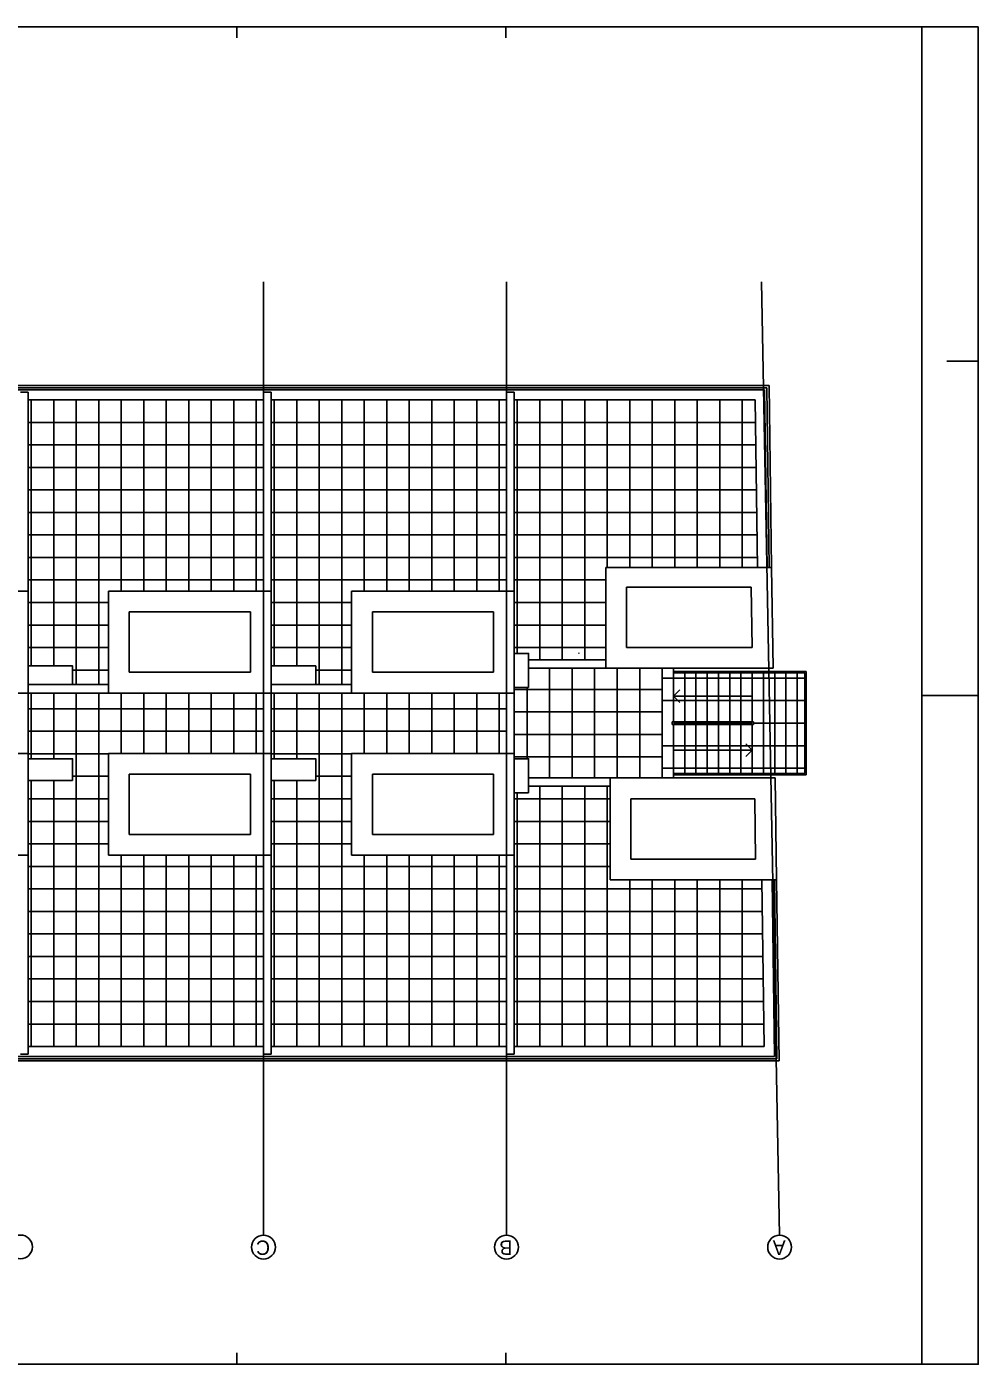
# Model space of a CAD drawing. Extents: x 1278 to 1356, y -443 to -224.
# Drawn here: x 1334.82 to 1355.97, y -253.66 to -223.96 of the extents above; entities that cross this region are included whole.
import ezdxf

# ---------------------------------------------------------------- set-up
doc = ezdxf.new("R2010")
doc.units = 0
for name, color, linetype in [('estrutura-eixos', 7, 'Continuous'), ('Level 10', 7, 'Continuous'), ('Level 2', 7, 'Continuous'), ('Level 21', 7, 'Continuous'), ('Level 60', 7, 'Continuous'), ('Level 62', 7, 'Continuous'), ('Level 66', 7, 'Continuous'), ('Level 68', 7, 'Continuous'), ('Level 70', 7, 'Continuous')]:
    doc.layers.add(name, color=color, linetype=linetype)

msp = doc.modelspace()

# ---------------------------------------------------------------- linework, layer by layer
at = {"layer": 'estrutura-eixos'}
for p, q in [((1340.084, -229.62), (1340.084, -250.792)), ((1345.484, -250.792), (1345.484, -229.62)), ((1351.148, -229.62), (1351.553, -250.792))]:
    msp.add_line(p, q, dxfattribs=at)
at = {"layer": 'Level 10'}
for p, q in [((1348.943, -240.624), (1348.943, -238.224)), ((1352.113, -238.424), (1348.943, -238.424)), ((1349.193, -239.394), (1349.193, -238.224)), ((1349.443, -239.394), (1349.443, -238.304)), ((1349.693, -239.394), (1349.693, -238.304)), ((1349.943, -239.394), (1349.943, -238.304)), ((1350.193, -239.394), (1350.193, -238.304)), ((1350.443, -239.394), (1350.443, -238.304)), ((1350.693, -239.394), (1350.693, -238.304)), ((1350.943, -239.394), (1350.943, -238.304)), ((1351.193, -240.544), (1351.193, -238.304)), ((1351.443, -240.544), (1351.443, -238.304)), ((1351.693, -240.544), (1351.693, -238.304)), ((1351.943, -240.544), (1351.943, -238.304)), ((1352.113, -238.924), (1348.943, -238.924)), ((1349.193, -240.624), (1349.193, -239.454)), ((1349.443, -240.544), (1349.443, -239.454)), ((1349.693, -240.544), (1349.693, -239.454)), ((1349.943, -240.544), (1349.943, -239.454)), ((1350.693, -240.544), (1350.693, -239.454)), ((1350.943, -240.544), (1350.943, -239.454)), ((1352.113, -239.424), (1350.973, -239.424)), ((1352.113, -239.924), (1348.943, -239.924)), ((1352.113, -240.424), (1348.943, -240.424))]:
    msp.add_line(p, q, dxfattribs=at)
at = {"layer": 'Level 2'}
for p, q in [((1318.543, -231.924), (1345.543, -231.924)), ((1351.318, -231.924), (1345.543, -231.924)), ((1351.318, -231.924), (1351.374, -235.964)), ((1334.854, -232.244), (1340.083, -232.244)), ((1340.254, -232.244), (1345.483, -232.244)), ((1351.268, -231.974), (1345.543, -231.974)), ((1351.219, -232.024), (1345.543, -232.024)), ((1351.007, -232.244), (1345.654, -232.244)), ((1351.007, -232.244), (1351.058, -235.964)), ((1351.219, -232.024), (1351.274, -235.964)), ((1351.268, -231.974), (1351.324, -235.964)), ((1348.152, -236.406), (1350.92, -236.406)), ((1348.152, -236.406), (1348.152, -237.746)), ((1337.103, -236.954), (1339.794, -236.954)), ((1337.103, -236.954), (1337.103, -238.294)), ((1342.503, -236.954), (1345.194, -236.954)), ((1342.503, -236.954), (1342.503, -238.294)), ((1348.152, -237.746), (1350.939, -237.746)), ((1337.103, -238.294), (1339.794, -238.294)), ((1342.503, -238.294), (1345.194, -238.294)), ((1349.193, -238.224), (1349.193, -239.394)), ((1349.193, -238.274), (1352.143, -238.274)), ((1349.193, -238.304), (1352.113, -238.304)), ((1349.443, -238.304), (1349.443, -239.394)), ((1349.693, -238.304), (1349.693, -239.394)), ((1349.943, -238.304), (1349.943, -239.394)), ((1350.193, -238.304), (1350.193, -239.394)), ((1350.443, -238.304), (1350.443, -239.394)), ((1350.693, -238.304), (1350.693, -239.394)), ((1350.943, -238.304), (1350.943, -239.394)), ((1352.113, -238.304), (1352.113, -240.544)), ((1352.143, -238.274), (1352.143, -240.574)), ((1349.335, -238.683), (1349.193, -238.824)), ((1350.943, -238.824), (1349.193, -238.824)), ((1349.335, -238.965), (1349.193, -238.824)), ((1349.163, -239.394), (1350.973, -239.394)), ((1349.163, -239.394), (1349.163, -239.454)), ((1349.163, -239.454), (1350.973, -239.454)), ((1349.193, -239.424), (1350.943, -239.424)), ((1349.193, -239.454), (1349.193, -240.574)), ((1349.443, -239.454), (1349.443, -240.544)), ((1349.693, -239.454), (1349.693, -240.544)), ((1349.943, -239.454), (1349.943, -240.544)), ((1350.193, -239.454), (1350.193, -240.544)), ((1350.443, -239.454), (1350.443, -240.544)), ((1350.693, -239.454), (1350.693, -240.544)), ((1350.943, -239.454), (1350.943, -240.544)), ((1350.973, -239.394), (1350.973, -239.454)), ((1350.802, -239.883), (1350.943, -240.024)), ((1349.193, -240.024), (1350.943, -240.024)), ((1350.802, -240.165), (1350.943, -240.024)), ((1337.103, -240.554), (1339.794, -240.554)), ((1337.103, -240.554), (1337.103, -241.894)), ((1342.503, -240.554), (1345.194, -240.554)), ((1342.503, -240.554), (1342.503, -241.894)), ((1349.193, -240.544), (1352.113, -240.544)), ((1349.193, -240.574), (1349.193, -240.624)), ((1349.193, -240.574), (1352.143, -240.574)), ((1348.245, -241.104), (1351.001, -241.104)), ((1348.245, -241.104), (1348.245, -242.444)), ((1337.103, -241.894), (1339.794, -241.894)), ((1342.503, -241.894), (1345.194, -241.894)), ((1348.245, -242.444), (1351.02, -242.444)), ((1351.156, -242.908), (1351.207, -246.604)), ((1351.386, -242.904), (1351.441, -246.824)), ((1351.436, -242.904), (1351.492, -246.874)), ((1351.486, -242.904), (1351.543, -246.924)), ((1334.854, -246.604), (1340.083, -246.604)), ((1340.254, -246.604), (1345.483, -246.604)), ((1351.207, -246.604), (1345.654, -246.604)), ((1351.441, -246.824), (1345.493, -246.824)), ((1351.492, -246.874), (1345.493, -246.874)), ((1351.543, -246.924), (1345.493, -246.924))]:
    msp.add_line(p, q, dxfattribs=at)
at = {"layer": 'Level 21'}
for p, q in [((1334.923, -238.154), (1334.923, -232.244)), ((1335.423, -238.154), (1335.423, -232.244)), ((1335.923, -238.564), (1335.923, -232.244)), ((1336.423, -238.564), (1336.423, -232.244)), ((1336.923, -236.494), (1336.923, -232.244)), ((1337.423, -236.494), (1337.423, -232.244)), ((1337.923, -236.494), (1337.923, -232.244)), ((1338.423, -236.494), (1338.423, -232.244)), ((1338.923, -236.494), (1338.923, -232.244)), ((1339.423, -236.494), (1339.423, -232.244)), ((1339.923, -236.494), (1339.923, -232.244)), ((1340.323, -238.154), (1340.323, -232.244)), ((1340.823, -238.154), (1340.823, -232.244)), ((1341.323, -238.564), (1341.323, -232.244)), ((1341.823, -238.564), (1341.823, -232.244)), ((1342.323, -236.494), (1342.323, -232.244)), ((1342.823, -236.494), (1342.823, -232.244)), ((1343.323, -236.494), (1343.323, -232.244)), ((1343.823, -236.494), (1343.823, -232.244)), ((1344.323, -236.494), (1344.323, -232.244)), ((1344.823, -236.494), (1344.823, -232.244)), ((1345.323, -236.494), (1345.323, -232.244)), ((1345.723, -237.874), (1345.723, -232.244)), ((1346.223, -238.016), (1346.223, -232.244)), ((1346.723, -238.016), (1346.723, -232.244)), ((1347.223, -238.016), (1347.223, -232.244)), ((1347.723, -235.964), (1347.723, -232.244)), ((1348.223, -235.964), (1348.223, -232.244)), ((1348.723, -235.964), (1348.723, -232.244)), ((1349.223, -235.964), (1349.223, -232.244)), ((1349.723, -235.964), (1349.723, -232.244)), ((1350.223, -235.964), (1350.223, -232.244)), ((1350.723, -235.964), (1350.723, -232.244)), ((1334.854, -232.744), (1340.083, -232.744)), ((1340.254, -232.744), (1345.483, -232.744)), ((1345.654, -232.744), (1351.014, -232.744)), ((1334.854, -233.244), (1340.083, -233.244)), ((1340.254, -233.244), (1345.483, -233.244)), ((1345.654, -233.244), (1351.021, -233.244)), ((1334.854, -233.744), (1340.083, -233.744)), ((1340.254, -233.744), (1345.483, -233.744)), ((1345.654, -233.744), (1351.028, -233.744)), ((1334.854, -234.244), (1340.083, -234.244)), ((1340.254, -234.244), (1345.483, -234.244)), ((1345.654, -234.244), (1351.035, -234.244)), ((1334.854, -234.744), (1340.083, -234.744)), ((1340.254, -234.744), (1345.483, -234.744)), ((1345.654, -234.744), (1351.042, -234.744)), ((1334.854, -235.244), (1340.083, -235.244)), ((1340.254, -235.244), (1345.483, -235.244)), ((1345.654, -235.244), (1351.048, -235.244)), ((1334.854, -235.744), (1340.083, -235.744)), ((1340.254, -235.744), (1345.483, -235.744)), ((1345.654, -235.744), (1351.055, -235.744)), ((1334.854, -236.244), (1340.083, -236.244)), ((1340.254, -236.244), (1345.483, -236.244)), ((1345.654, -236.244), (1347.692, -236.244)), ((1334.854, -236.744), (1336.643, -236.744)), ((1340.254, -236.744), (1342.043, -236.744)), ((1345.654, -236.744), (1347.692, -236.744)), ((1334.854, -237.244), (1336.643, -237.244)), ((1340.254, -237.244), (1342.043, -237.244)), ((1345.654, -237.244), (1347.692, -237.244)), ((1334.854, -237.744), (1336.643, -237.744)), ((1340.254, -237.744), (1342.043, -237.744)), ((1345.654, -237.744), (1347.692, -237.744)), ((1335.843, -238.244), (1336.643, -238.244)), ((1341.244, -238.244), (1342.043, -238.244)), ((1346.443, -238.206), (1346.443, -240.624)), ((1346.943, -238.206), (1346.943, -240.624)), ((1347.443, -238.206), (1347.443, -240.624)), ((1347.943, -238.206), (1347.943, -240.624)), ((1348.443, -238.206), (1348.443, -240.624)), ((1334.923, -238.754), (1334.923, -240.214)), ((1335.423, -238.754), (1335.423, -240.214)), ((1335.923, -238.754), (1335.923, -246.604)), ((1336.423, -238.754), (1336.423, -246.604)), ((1336.923, -238.754), (1336.923, -240.094)), ((1337.423, -238.754), (1337.423, -240.094)), ((1337.923, -238.754), (1337.923, -240.094)), ((1338.423, -238.754), (1338.423, -240.094)), ((1338.923, -238.754), (1338.923, -240.094)), ((1339.423, -238.754), (1339.423, -240.094)), ((1339.923, -238.754), (1339.923, -240.094)), ((1340.323, -238.754), (1340.323, -240.214)), ((1340.823, -238.754), (1340.823, -240.214)), ((1341.323, -238.754), (1341.323, -246.604)), ((1341.823, -238.754), (1341.823, -246.604)), ((1342.323, -238.754), (1342.323, -240.094)), ((1342.823, -238.754), (1342.823, -240.094)), ((1343.323, -238.754), (1343.323, -240.094)), ((1343.823, -238.754), (1343.823, -240.094)), ((1344.323, -238.754), (1344.323, -240.094)), ((1344.823, -238.754), (1344.823, -240.094)), ((1345.323, -238.754), (1345.323, -240.094)), ((1348.943, -238.674), (1345.654, -238.674)), ((1345.943, -238.634), (1345.943, -240.214)), ((1334.854, -239.104), (1340.083, -239.104)), ((1340.254, -239.104), (1345.483, -239.104)), ((1348.943, -239.174), (1345.654, -239.174)), ((1334.854, -239.604), (1340.083, -239.604)), ((1340.254, -239.604), (1345.483, -239.604)), ((1348.943, -239.674), (1345.654, -239.674)), ((1334.854, -240.104), (1336.643, -240.104)), ((1340.254, -240.104), (1342.043, -240.104)), ((1348.943, -240.174), (1345.654, -240.174)), ((1334.923, -240.694), (1334.923, -246.604)), ((1335.423, -240.694), (1335.423, -246.604)), ((1335.843, -240.604), (1336.643, -240.604)), ((1340.323, -240.694), (1340.323, -246.604)), ((1340.823, -240.694), (1340.823, -246.604)), ((1341.244, -240.604), (1342.043, -240.604)), ((1346.223, -240.824), (1346.223, -246.604)), ((1346.723, -240.824), (1346.723, -246.604)), ((1347.223, -240.824), (1347.223, -246.604)), ((1347.723, -240.824), (1347.723, -246.604)), ((1334.854, -241.104), (1336.643, -241.104)), ((1340.254, -241.104), (1342.043, -241.104)), ((1345.654, -241.104), (1347.785, -241.104)), ((1345.723, -240.974), (1345.723, -246.604)), ((1334.854, -241.604), (1336.643, -241.604)), ((1340.254, -241.604), (1342.043, -241.604)), ((1345.654, -241.604), (1347.785, -241.604)), ((1334.854, -242.104), (1336.643, -242.104)), ((1340.254, -242.104), (1342.043, -242.104)), ((1345.654, -242.104), (1347.785, -242.104)), ((1334.854, -242.604), (1340.083, -242.604)), ((1336.923, -242.354), (1336.923, -246.604)), ((1337.423, -242.354), (1337.423, -246.604)), ((1337.923, -242.354), (1337.923, -246.604)), ((1338.423, -242.354), (1338.423, -246.604)), ((1338.923, -242.354), (1338.923, -246.604)), ((1339.423, -242.354), (1339.423, -246.604)), ((1339.923, -242.354), (1339.923, -246.604)), ((1340.254, -242.604), (1345.483, -242.604)), ((1342.323, -242.354), (1342.323, -246.604)), ((1342.823, -242.354), (1342.823, -246.604)), ((1343.323, -242.354), (1343.323, -246.604)), ((1343.823, -242.354), (1343.823, -246.604)), ((1344.323, -242.354), (1344.323, -246.604)), ((1344.823, -242.354), (1344.823, -246.604)), ((1345.323, -242.354), (1345.323, -246.604)), ((1345.654, -242.604), (1347.785, -242.604)), ((1348.223, -242.904), (1348.223, -246.604)), ((1348.723, -242.904), (1348.723, -246.604)), ((1349.223, -242.904), (1349.223, -246.604)), ((1349.723, -242.904), (1349.723, -246.604)), ((1350.223, -242.904), (1350.223, -246.604)), ((1350.723, -242.904), (1350.723, -246.604)), ((1334.854, -243.104), (1340.083, -243.104)), ((1340.254, -243.104), (1345.483, -243.104)), ((1345.654, -243.104), (1351.158, -243.104)), ((1334.854, -243.604), (1340.083, -243.604)), ((1340.254, -243.604), (1345.483, -243.604)), ((1345.654, -243.604), (1351.165, -243.604)), ((1334.854, -244.104), (1340.083, -244.104)), ((1340.254, -244.104), (1345.483, -244.104)), ((1345.654, -244.104), (1351.172, -244.104)), ((1334.854, -244.604), (1340.083, -244.604)), ((1340.254, -244.604), (1345.483, -244.604)), ((1345.654, -244.604), (1351.179, -244.604)), ((1334.854, -245.104), (1340.083, -245.104)), ((1340.254, -245.104), (1345.483, -245.104)), ((1345.654, -245.104), (1351.186, -245.104)), ((1334.854, -245.604), (1340.083, -245.604)), ((1340.254, -245.604), (1345.483, -245.604)), ((1345.654, -245.604), (1351.193, -245.604)), ((1334.854, -246.104), (1340.083, -246.104)), ((1340.254, -246.104), (1345.483, -246.104)), ((1345.654, -246.104), (1351.2, -246.104))]:
    msp.add_line(p, q, dxfattribs=at)
at = {"layer": 'Level 60'}
for centre in [(1334.684, -251.055), (1340.084, -251.058), (1345.484, -251.058), (1351.553, -251.058)]:
    msp.add_circle(centre, 0.265, dxfattribs=at)
at = {"layer": 'Level 62'}
for p, q in [((1339.491, -224.209), (1339.491, -223.959)), ((1345.466, -224.209), (1345.466, -223.959)), ((1354.716, -253.659), (1354.716, -223.959)), ((1355.966, -231.384), (1355.266, -231.384)), ((1354.716, -238.809), (1355.966, -238.809)), ((1339.491, -253.409), (1339.491, -253.659)), ((1345.466, -253.409), (1345.466, -253.659)), ((1354.716, -253.659), (1355.966, -253.659))]:
    msp.add_line(p, q, dxfattribs=at)
msp.add_lwpolyline([(1355.966, -223.959), (1355.966, -253.659), (1278.016, -253.659), (1278.016, -223.959)], close=True, dxfattribs=at)
at = {"layer": 'Level 66'}
msp.add_line((1348.943, -240.634), (1348.943, -238.206), dxfattribs=at)
at = {"layer": 'Level 68'}
msp.add_line((1347.092, -237.859), (1347.093, -237.874), dxfattribs=at)
at = {"layer": 'Level 70'}
for p, q in [((1345.543, -231.974), (1318.543, -231.974)), ((1345.543, -232.024), (1318.543, -232.024)), ((1334.854, -232.074), (1334.683, -232.074)), ((1334.854, -232.074), (1334.854, -238.564)), ((1340.083, -232.074), (1340.083, -236.494)), ((1340.254, -232.074), (1340.083, -232.074)), ((1340.254, -232.074), (1340.254, -238.564)), ((1345.654, -232.074), (1345.483, -232.074)), ((1345.483, -232.074), (1345.483, -236.494)), ((1345.654, -232.074), (1345.654, -238.206)), ((1351.374, -235.964), (1347.692, -235.964)), ((1347.692, -235.964), (1347.692, -238.206)), ((1351.374, -235.964), (1351.406, -238.206)), ((1350.92, -236.406), (1350.939, -237.746)), ((1331.243, -236.494), (1334.854, -236.494)), ((1336.643, -236.494), (1336.643, -238.754)), ((1336.643, -236.494), (1340.254, -236.494)), ((1342.043, -236.494), (1342.043, -238.754)), ((1342.043, -236.494), (1345.654, -236.494)), ((1339.794, -238.294), (1339.794, -236.954)), ((1345.194, -238.294), (1345.194, -236.954)), ((1345.974, -238.016), (1347.692, -238.016)), ((1345.654, -238.206), (1345.654, -240.824)), ((1345.974, -238.206), (1351.406, -238.206)), ((1329.282, -238.754), (1334.854, -238.754)), ((1336.643, -238.564), (1334.854, -238.564)), ((1334.854, -238.564), (1334.854, -246.774)), ((1334.854, -238.754), (1340.254, -238.754)), ((1340.083, -240.094), (1340.083, -238.754)), ((1340.254, -238.564), (1340.254, -246.774)), ((1342.043, -238.564), (1340.254, -238.564)), ((1340.254, -238.754), (1345.654, -238.754)), ((1345.483, -240.094), (1345.483, -238.754)), ((1331.243, -240.094), (1334.854, -240.094)), ((1336.643, -242.354), (1336.643, -240.094)), ((1336.643, -240.094), (1340.254, -240.094)), ((1342.043, -242.354), (1342.043, -240.094)), ((1342.043, -240.094), (1345.654, -240.094)), ((1339.794, -241.894), (1339.794, -240.554)), ((1345.194, -241.894), (1345.194, -240.554)), ((1345.654, -240.824), (1345.654, -246.774)), ((1351.455, -240.634), (1345.974, -240.634)), ((1347.785, -240.824), (1345.974, -240.824)), ((1347.785, -242.904), (1347.785, -240.634)), ((1351.455, -240.634), (1351.486, -242.904)), ((1351.001, -241.104), (1351.02, -242.444)), ((1331.243, -242.354), (1334.854, -242.354)), ((1336.643, -242.354), (1340.254, -242.354)), ((1340.083, -246.774), (1340.083, -242.354)), ((1342.043, -242.354), (1345.654, -242.354)), ((1345.483, -246.774), (1345.483, -242.354)), ((1351.486, -242.904), (1347.785, -242.904)), ((1334.854, -246.774), (1334.683, -246.774)), ((1340.254, -246.774), (1340.083, -246.774)), ((1345.483, -246.774), (1345.654, -246.774)), ((1345.543, -246.824), (1323.919, -246.824)), ((1345.543, -246.874), (1323.919, -246.874)), ((1323.943, -246.924), (1345.543, -246.924)), ((1345.593, -246.924), (1345.493, -246.924))]:
    msp.add_line(p, q, dxfattribs=at)
for points in [[(1345.974, -238.634), (1345.654, -238.634), (1345.654, -237.874), (1345.974, -237.874)], [(1335.843, -238.564), (1334.854, -238.564), (1334.854, -238.154), (1335.843, -238.154)], [(1341.244, -238.564), (1340.254, -238.564), (1340.254, -238.154), (1341.244, -238.154)], [(1335.843, -240.694), (1334.854, -240.694), (1334.854, -240.214), (1335.843, -240.214)], [(1341.244, -240.694), (1340.254, -240.694), (1340.254, -240.214), (1341.244, -240.214)], [(1345.974, -240.974), (1345.654, -240.974), (1345.654, -240.214), (1345.974, -240.214)]]:
    msp.add_lwpolyline(points, close=True, dxfattribs=at)

# ---------------------------------------------------------------- texts
at = {"layer": 'Level 60'}
for s, p in [('C', (1340.229, -250.911)), ('B', (1345.611, -250.911)), ('A', (1351.686, -250.911))]:
    msp.add_text(s, height=0.32, rotation=180, dxfattribs=at).set_placement(p)

doc.saveas('drawing.dxf')
